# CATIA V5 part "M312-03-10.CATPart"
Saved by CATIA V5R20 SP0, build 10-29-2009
Part number: M312-03-10
Revision: TUTTO
Definition: NON CONOSCIUTO
Nomenclature: M312-03-10
Source: Unknown
Bounding box of the stored display mesh (mm): x -12.5 to 12.5, y -12.31 to 12.31, z -15.8 to 94.2
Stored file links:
  C:\Users\Utente\Desktop\IO LAVORO\3D X SITO CF\X SITO\M312-03\M312-03-10.CATPart
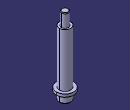
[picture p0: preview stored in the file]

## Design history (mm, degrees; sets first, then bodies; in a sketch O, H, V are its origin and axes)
Body1 "Sposta faccia1" (main body)
  Solid1: solid without history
